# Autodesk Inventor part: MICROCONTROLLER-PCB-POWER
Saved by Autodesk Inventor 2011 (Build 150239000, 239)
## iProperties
Created: 2010-06
Part Number: MICROCONTROLLER-PCB-POWER
Document SubType Name: Modeling
Designer: kurdi
Density: 1 g/cm^3
Author: kurdi
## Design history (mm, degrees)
feature "Base1"
node "NONE"
